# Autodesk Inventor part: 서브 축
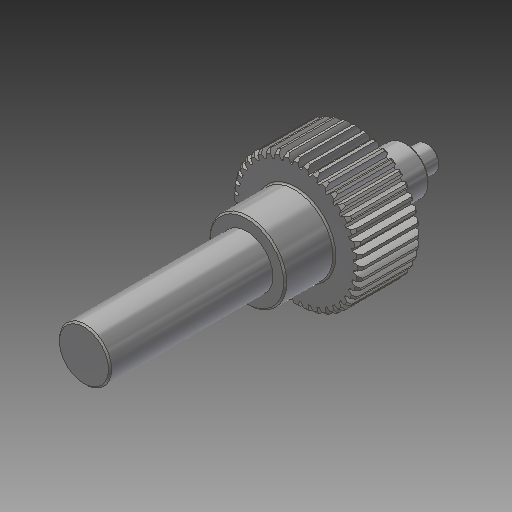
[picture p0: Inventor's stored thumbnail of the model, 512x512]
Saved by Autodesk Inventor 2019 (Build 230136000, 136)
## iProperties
Created: 2016-02
Part Number: 서브 축
Material: 강철, 연강
Document SubType Name: Modeling
Designer: mdu
Categories: <?xml version="1.0" encoding="UTF-16"?> <MemberInstance><Categories><FamilyTemplate><FamilyTemplateParameter ValueType="xs:double" Id="1" ObjectReferenceKey="da
Density: 7.86 g/cm^3
Appearance: 강철
CustomPartVersion: 1
Author: mdu
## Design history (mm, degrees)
sketch "Sketch1"
  geometry: C1 r 21 at (0, 0)
  constraints: 1 centre point
  dimensions: "d0" = 42 diameter of C1 (= da_da)
extrude "Extrusion1" new body sketch "Sketch1" distance "d1" = 20 (= da_b); taper "d2" = 0 deg
workplane "Work Plane2"
feature "피치 지름" dims "d4" = 10, "d5" = 0
workplane "Work Plane8"
workplane "Work Plane9"
chamfer "모따기1" distance "d49" = 1; stored, may be unused: second distance "d50" = 2, angle "d51" = 45 deg
sketch "스케치3"
  geometry: C1 r 12.5 at (0, 0); 1 further point
  constraints: 1 centre point, 1 coincident
  dimensions: "d52" = 25 diameter of C1
extrude "돌출2" join sketch "스케치3" distance "d53" = 16; taper "d54" = 0 deg
sketch "스케치4"
  geometry: C1 r 8.5 at (0, 0); 1 further point
  constraints: 1 centre point, 1 coincident
  dimensions: "d55" = 17 diameter of C1
extrude "돌출3" join sketch "스케치4" distance "d56" = 53; taper "d57" = 0 deg
sketch "스케치5"
  geometry: C1 r 7.5 at (0, 0); 1 further point
  constraints: 1 centre point, 1 coincident
  dimensions: "d62" = 15 diameter of C1
extrude "돌출4" join sketch "스케치5" distance "d63" = 16; taper "d64" = 0 deg
sketch "스케치6"
  geometry: C1 r 4 at (0, 0); 1 further point
  constraints: 1 centre point, 1 coincident
  dimensions: "d65" = 8 diameter of C1
extrude "돌출5" join sketch "스케치6" distance "d66" = 7; taper "d67" = 0 deg
chamfer "모따기2" distance "d58" = 0.5; stored, may be unused: second distance "d59" = 2, angle "d60" = 45 deg
fillet "모깎기1" dims "d61" = 0.5
feature "스퍼 기어" dims "da_b" = 20, "da_d" = 40, "da_aw" = 31, "da_da" = 42, "da_df" = 37.5, "da_dw" = 40, angle "da_beta" = 0 deg, "da_lefttooth" = 0, "da_righttooth" = 0
body "Solid1"
sketch "Sketch2"
  geometry: C1 r 21 at (0, 0) reference; C2 r 20 at (0, 0)
  constraints: 1 centre point, 1 coincident
  dimensions: "d3" = 40 diameter of C2 (= da_dw)
body "Srf1"
other parameters: "d16" = 31 (= da_aw), "d17" = 0, "d34" = 4.5 deg (computed from da_z), "d39" = 0, "d41" = 0, "d43" = 31 (= da_aw), "d46" = 31 (= da_aw), "d47" = 0, "d48" = 0
